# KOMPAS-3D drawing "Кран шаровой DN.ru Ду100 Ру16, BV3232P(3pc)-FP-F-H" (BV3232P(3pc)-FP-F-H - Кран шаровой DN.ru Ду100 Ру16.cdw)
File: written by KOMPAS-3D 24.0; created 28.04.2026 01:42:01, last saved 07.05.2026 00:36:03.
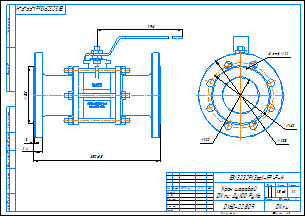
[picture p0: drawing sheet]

Document properties: Автор: Максим; Форматы листов документа: A3; Полное имя файла: BVxxP(3pc)-FP-F-H - Кран шаровой DN.ru Ду100 Ру16.cdw; Масса: 25.675; Наименование: Кран шаровой DN.ru Ду100 Ру16; Количество листов документа: 1; Примечание: D160-22809

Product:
- Body: Тело 1  | qty 1
    Масса: 22.220503
- Part/product: Кран шаровой DN.ru Ду100 Ру16  | designation BV3232P(3pc)-FP-F-H
    Масса: 25.675
    Раздел спецификации: Прочие изделия
    Форматы листов документа: A3
    Примечание: D160-22809

Views: Вид 1, Вид:2, Проекционный вид 2, Вид:1
Referenced files in D:\Rabota ebanaya\Апрель\BVxxP(3pc)-FP-F-H Кран шаровой Ду15-100\Исходники\DN100\: BVxxP(3pc)-FP-F-H - Кран шаровой DN.ru Ду100 Ру16.m3d, BVxxP(3pc)-FP-F-H - Кран шаровой DN.ru Ду100 Ру16.cdw
Referenced files in D:\Rabota ebanaya\Апрель\BV3232P(3pc)-FP-F-H Кран шаровой Ду15-100\Исходники\DN100\: BV3232P(3pc)-FP-F-H - Кран шаровой DN.ru Ду100 Ру16.m3d
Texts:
  Линейный размер
  BV3232P(3pc)-FP-F-H
  Диаметральный размер
  Кран шаровой
  DN.ru Ду100 Ру16
  Кран шаровой DN.ru Ду100 Ру16
  BV3232P(3pc)-FP-F-H Кран шаровой DN.ru Ду100 Ру16
Dimensions and other numbers on the sheet: 0; 3; 2; 4; 350±1,5; 298; 24; 158; 235; 100; 180; 8 отв.; 22; 1:2; 1; 25,68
